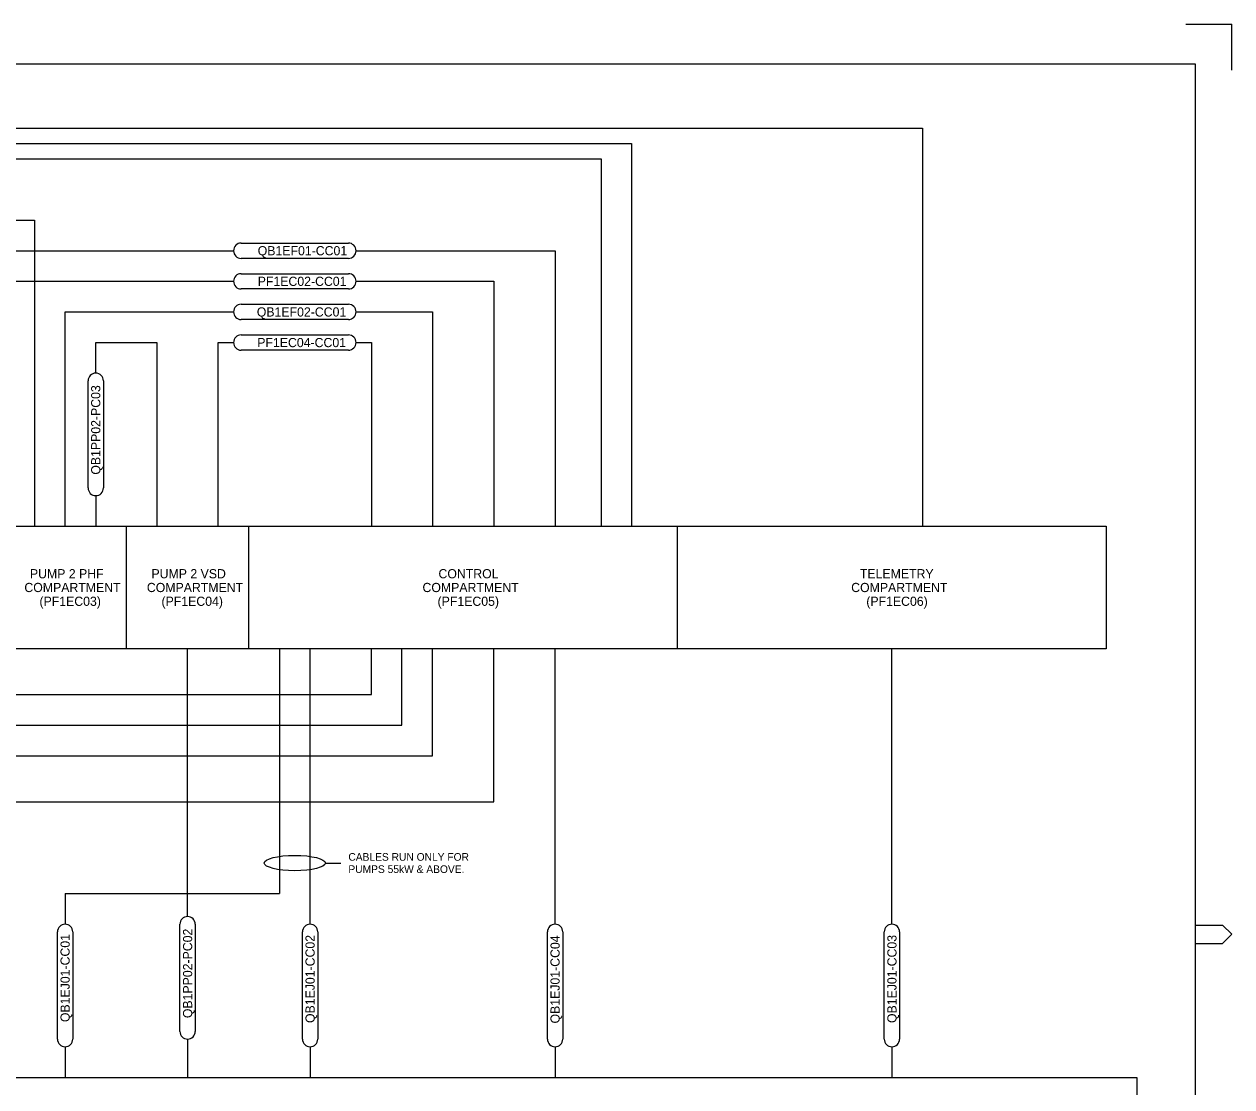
# Model space of a CAD drawing. Extents: x 0 to 841, y 0 to 594.
# Drawn here: x 446.6 to 841, y 246.9 to 594 of the extents above; entities that cross this region are included whole.
import ezdxf

# ---------------------------------------------------------------- set-up
doc = ezdxf.new("R2010")
doc.units = 0
doc.layers.add('A1BORDER', color=7, linetype='Continuous')
doc.layers.add('INSTALLED', color=7, linetype='Continuous')

msp = doc.modelspace()

# ---------------------------------------------------------------- linework, layer by layer
at = {"layer": 'A1BORDER'}
for p, q in [((826, 594), (841, 594)), ((841, 579), (841, 594)), ((28, 581), (829, 581)), ((829, 581), (829, 15)), ((829, 299.76), (838, 299.76)), ((838, 299.76), (841, 296.76)), ((838, 293.76), (841, 296.76)), ((829, 293.76), (838, 293.76))]:
    msp.add_line(p, q, dxfattribs=at)
at = {"layer": 'INSTALLED'}
for p, q in [((320, 560), (740, 560)), ((740, 560), (740, 430)), ((330, 555), (645, 555)), ((645, 555), (645, 430)), ((340, 550), (635, 550)), ((635, 550), (635, 430)), ((300, 530), (450, 530)), ((450, 530), (450, 430)), ((517.5, 522.5), (552.5, 522.5)), ((380, 520), (515, 520)), ((552.5, 517.5), (517.5, 517.5)), ((555, 520), (620, 520)), ((620, 520), (620, 430)), ((430, 510), (515, 510)), ((517.5, 512.5), (552.5, 512.5)), ((555, 510), (600, 510)), ((600, 510), (600, 430)), ((552.5, 507.5), (517.5, 507.5)), ((517.5, 502.5), (552.5, 502.5)), ((460, 430), (460, 500)), ((460, 500), (515, 500)), ((552.5, 497.5), (517.5, 497.5)), ((555, 500), (580, 500)), ((580, 500), (580, 430)), ((470, 480), (470, 490)), ((470, 490), (490, 490)), ((490, 490), (490, 430)), ((510, 430), (510, 490)), ((510, 490), (515, 490)), ((517.5, 492.5), (552.5, 492.5)), ((555, 490), (560, 490)), ((560, 490), (560, 430)), ((552.5, 487.5), (517.5, 487.5)), ((467.5, 442.5), (467.5, 477.5)), ((472.5, 477.5), (472.5, 442.5)), ((470, 440), (470, 430)), ((480, 390), (480, 430)), ((520, 390), (520, 430)), ((660, 390), (660, 430)), ((500, 302.5), (500, 390)), ((530, 390), (530, 310)), ((540, 300), (540, 390)), ((560, 375), (560, 390)), ((570, 365), (570, 390)), ((580, 355), (580, 390)), ((600, 340), (600, 390)), ((620, 300), (620, 390)), ((730, 300), (730, 390)), ((400, 375), (560, 375)), ((400, 365), (570, 365)), ((400, 355), (580, 355)), ((400, 340), (600, 340)), ((545, 320), (550, 320)), ((460, 310), (530, 310)), ((460, 310), (460, 300)), ((497.5, 265), (497.5, 300)), ((502.5, 300), (502.5, 265)), ((457.5, 262.5), (457.5, 297.5)), ((462.5, 297.5), (462.5, 262.5)), ((537.5, 262.5), (537.5, 297.5)), ((542.5, 297.5), (542.5, 262.5)), ((617.5, 262.5), (617.5, 297.5)), ((622.5, 297.5), (622.5, 262.5)), ((727.5, 262.5), (727.5, 297.5)), ((732.5, 297.5), (732.5, 262.5)), ((500, 262.5), (500, 250)), ((460, 260), (460, 250)), ((540, 260), (540, 250)), ((620, 260), (620, 250)), ((730, 260), (730, 250))]:
    msp.add_line(p, q, dxfattribs=at)
for points in [[(360, 390), (360, 430), (800, 430), (800, 390)], [(400, 230), (400, 250), (810, 250), (810, 230)]]:
    msp.add_lwpolyline(points, close=True, dxfattribs=at)
for centre, start, end in [((517.5, 520), 90, 270), ((552.5, 520), 270, 90), ((517.5, 510), 90, 270), ((552.5, 510), 270, 90), ((517.5, 500), 90, 270), ((552.5, 500), 270, 90), ((517.5, 490), 90, 270), ((552.5, 490), 270, 90), ((470, 477.5), 0, 180), ((470, 442.5), 180, 0), ((460, 297.5), 0, 180), ((500, 300), 0, 180), ((540, 297.5), 0, 180), ((620, 297.5), 0, 180), ((730, 297.5), 0, 180), ((500, 265), 180, 0), ((460, 262.5), 180, 0), ((540, 262.5), 180, 0), ((620, 262.5), 180, 0), ((730, 262.5), 180, 0)]:
    msp.add_arc(centre, 2.5, start, end, dxfattribs=at)
msp.add_ellipse((535, 320), major_axis=(-10, 0), ratio=0.25, dxfattribs=at)

# ---------------------------------------------------------------- texts
for s, rotation, p in [('QB1EF01-CC01', 360, (522.9, 518.5)), ('PF1EC02-CC01', 360, (522.9, 508.5)), ('QB1EF02-CC01', 360, (522.6, 498.5)), ('PF1EC04-CC01', 360, (522.75, 488.5)), ('QB1PP02-PC03', 90, (471.5, 446.85)), ('PUMP 2 PHF', 360, (448.5, 413)), ('PUMP 2 VSD', 360, (488.2, 413)), ('CONTROL', 360, (581.93, 413)), ('TELEMETRY', 360, (719.54, 413)), ('COMPARTMENT', 360, (446.7, 408.5)), ('COMPARTMENT', 360, (486.7, 408.5)), ('COMPARTMENT', 360, (576.7, 408.5)), ('COMPARTMENT', 360, (716.7, 408.5)), ('(PF1EC03)', 360, (451.63, 404)), ('(PF1EC04)', 360, (491.48, 404)), ('(PF1EC05)', 360, (581.63, 404)), ('(PF1EC06)', 360, (721.63, 404)), ('QB1EJ01-CC01', 90, (461.5, 268.05)), ('QB1PP02-PC02', 90, (501.5, 269.35)), ('QB1EJ01-CC02', 90, (541.5, 267.75)), ('QB1EJ01-CC04', 90, (621.5, 267.6)), ('QB1EJ01-CC03', 90, (731.5, 267.75))]:
    msp.add_text(s, height=3, rotation=rotation, dxfattribs=at).set_placement(p)
for s, p in [('CABLES RUN ONLY FOR', (552.5, 320.75)), ('PUMPS 55kW & ABOVE.', (552.5, 316.75))]:
    msp.add_text(s, height=2.5, dxfattribs=at).set_placement(p)

doc.saveas('drawing.dxf')
